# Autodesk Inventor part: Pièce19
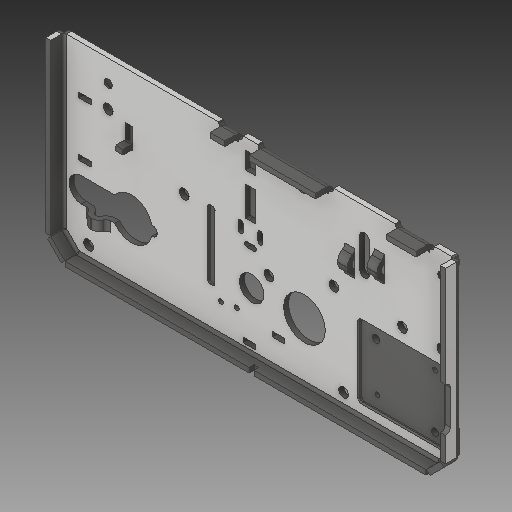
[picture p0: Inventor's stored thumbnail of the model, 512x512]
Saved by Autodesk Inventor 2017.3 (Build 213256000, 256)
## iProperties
Created: 2007-12
Part Number: Pièce19
Material: Générique
Document SubType Name: Modeling
Designer: ficho
Density: 1 g/cm^3
Appearance: Par défaut
Author: ficho
Sending System: SolidWorks 2009
Last Author: tof
Last Saved: 2010-08-03
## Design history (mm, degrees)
feature "Enlèv. mat.-Extru.30"
node "Solide1"
